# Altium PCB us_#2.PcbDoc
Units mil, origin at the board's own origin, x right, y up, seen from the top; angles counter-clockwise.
Board outline 1397.64 x 1968.5 mil, 2 copper layers (Top Layer, Bottom Layer); 60 components, 46 nets, 211 pads, 12 vias.
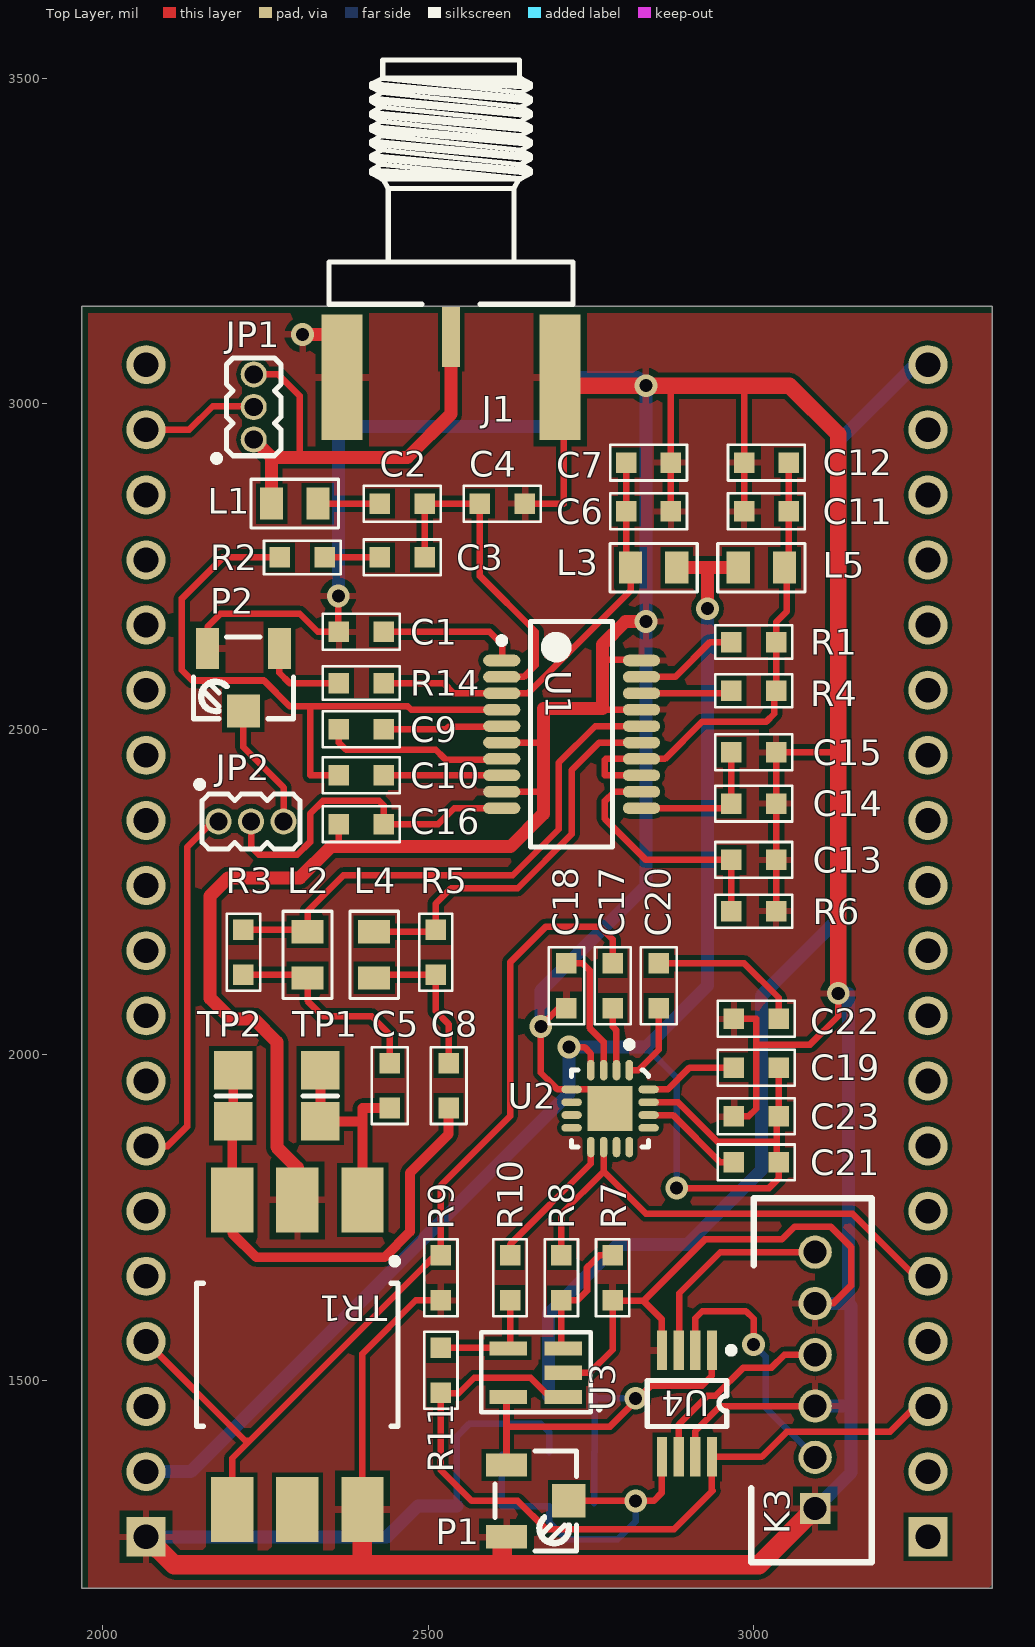
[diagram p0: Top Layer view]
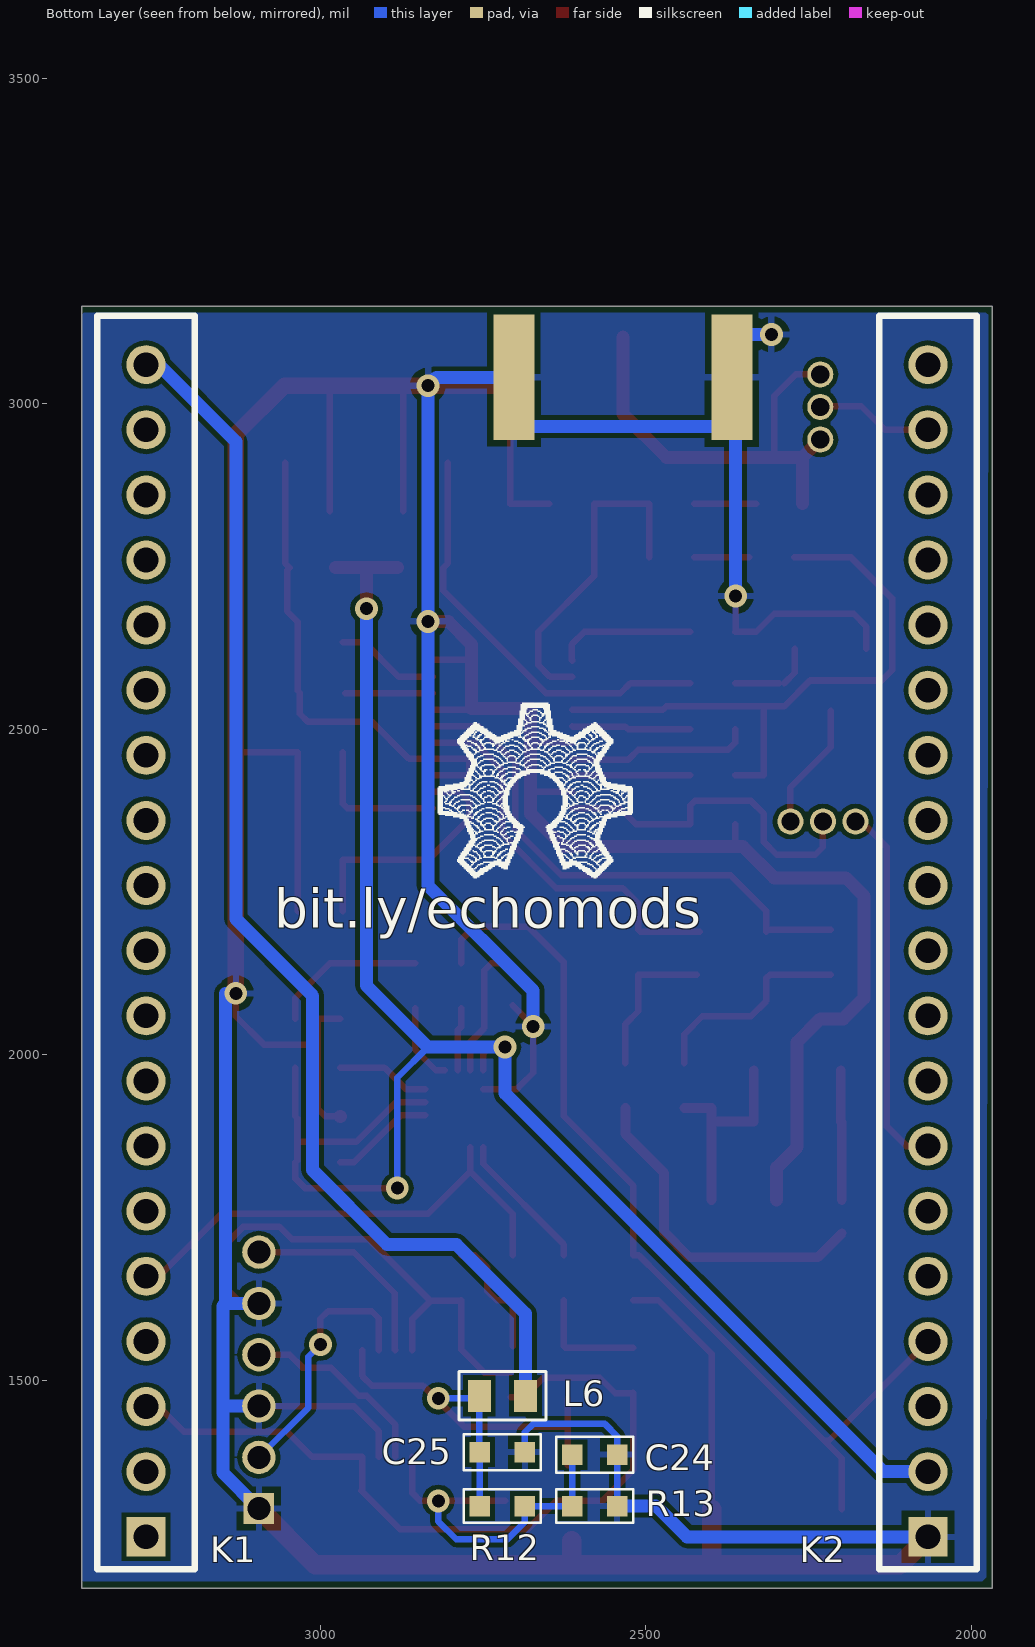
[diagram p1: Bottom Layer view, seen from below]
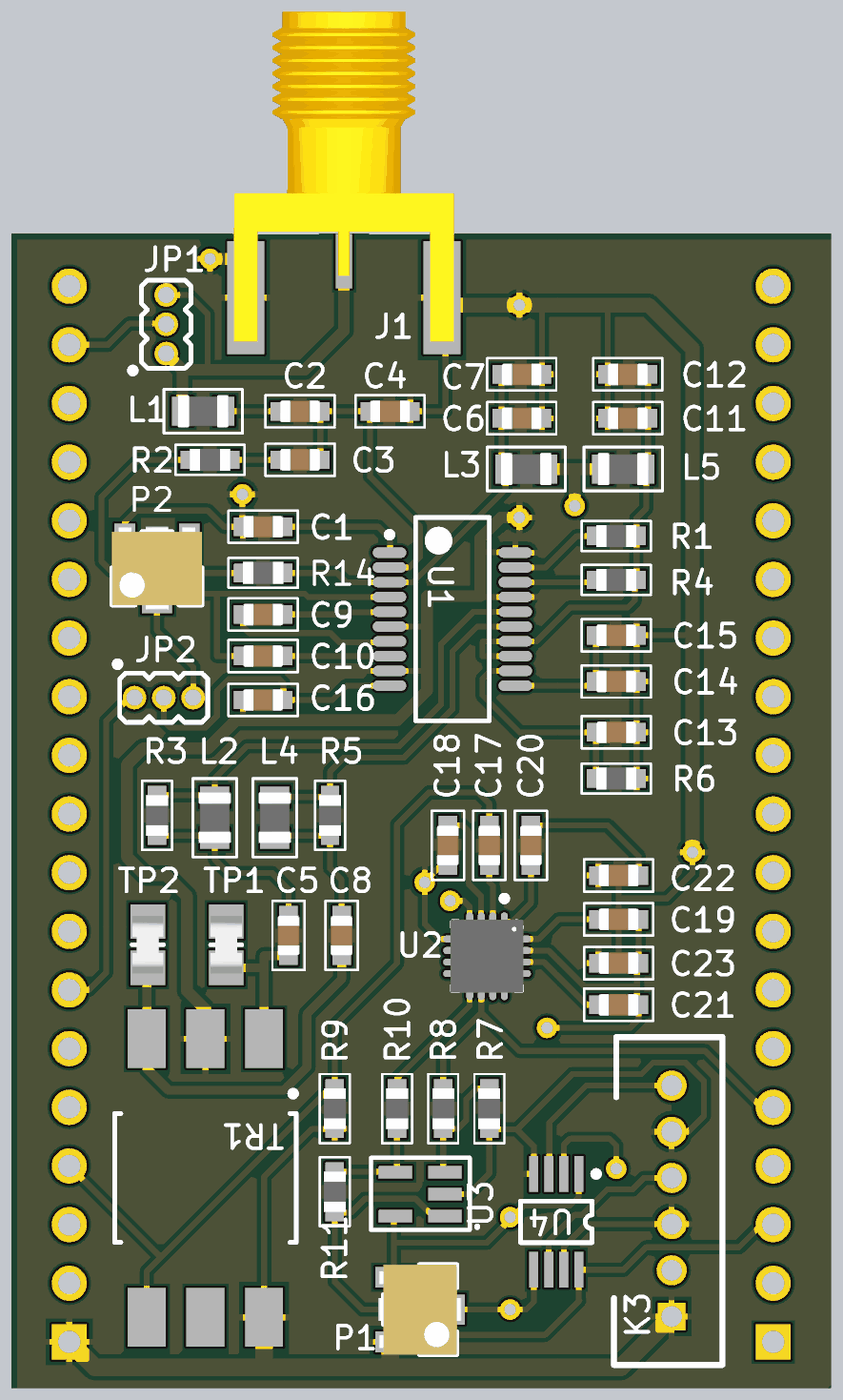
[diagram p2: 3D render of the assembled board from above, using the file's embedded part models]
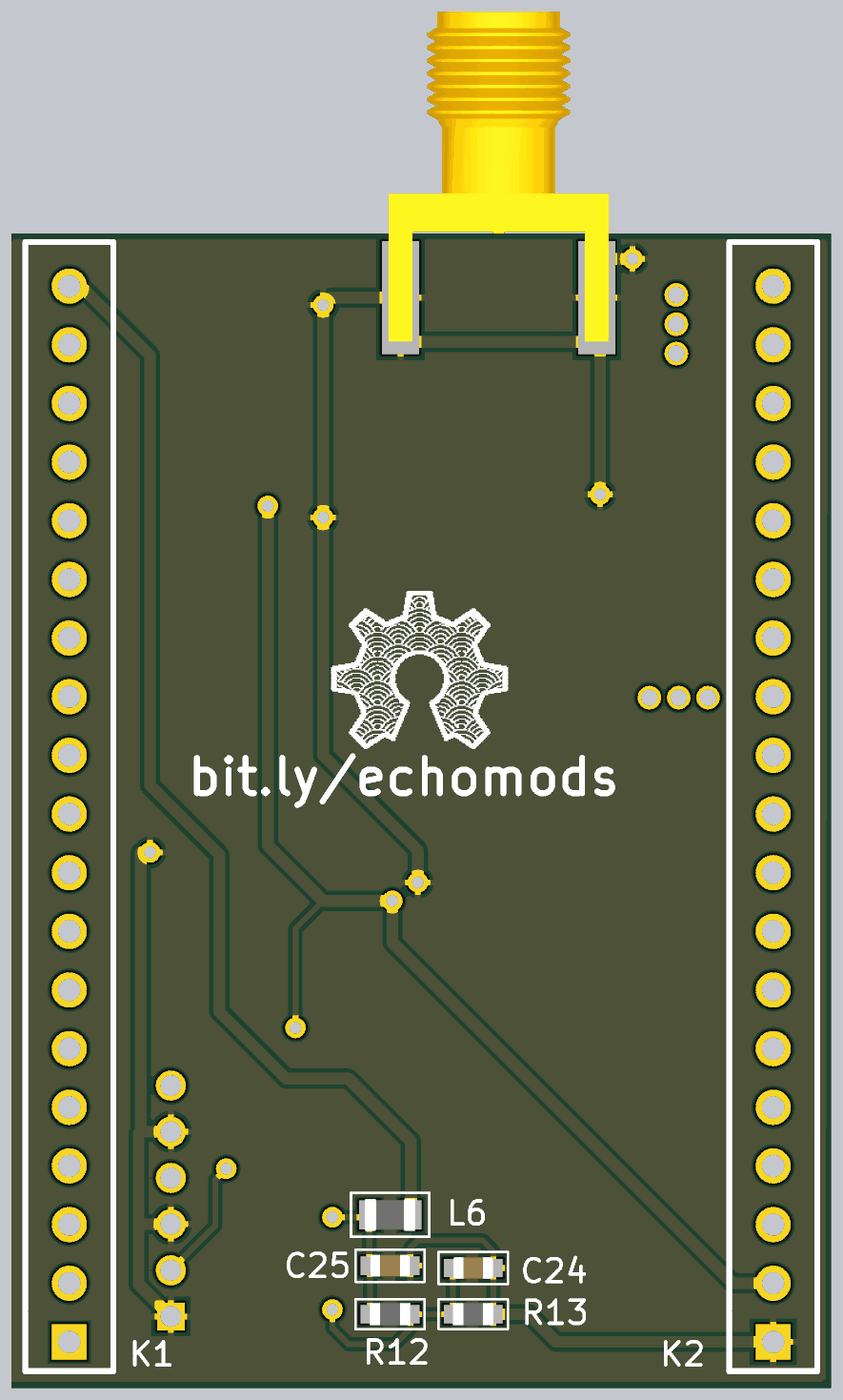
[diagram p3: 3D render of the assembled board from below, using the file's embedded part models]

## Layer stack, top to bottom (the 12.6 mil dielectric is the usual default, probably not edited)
Top Solder: solder mask 0.4, Solder Resist, Dk 3.5
Top Layer: signal copper 1.4
Dielectric 1: dielectric 12.6, FR-4, Dk 4.8
Bottom Layer: signal copper 1.4
Bottom Solder: solder mask 0.4, Solder Resist, Dk 3.5

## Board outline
1968.5,1181.1 3366.14,1181.1 3366.14,3149.61 1968.5,3149.61

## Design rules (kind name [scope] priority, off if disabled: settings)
Clearance [All] p1: gap=7
DiffPairsRouting [All] p1: maxlimit=10 minlimit=10 mostfreqgap=10 toplayer_minwidth=15 toplayer_maxwidth=15 toplayer_prefwidth=15 bottomlayer_minwidth=15 bottomlayer_maxwidth=15 bottomlayer_prefwidth=15 maxuncoupledlength=500
MinimumSolderMaskSliver [All] p1: minsoldermaskwidth=0
PolygonConnect [All] p1: connectstyle=Relief reliefconductorwidth=10 reliefentries=4 polygonreliefangle="90 Angle" airgapwidth=10
RoutingVias [All] p1: holewidth=20 width=35 viastyle="Through Hole" minholewidth=20 minwidth=35 maxholewidth=28 maxwidth=50
SilkToSilkClearance [All] p1: silktosilkclearance=7
SilkToSolderMaskClearance [IsPad] p1: minsilkscreentomaskgap=4 clearancetoexposedcopper=TRUE
SolderMaskExpansion [All] p1: expansion=4
Width [All] p1: maxlimit=40 minlimit=10 preferedwidth=10
25 further rules are at their usual default settings.

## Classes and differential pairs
net class RF: NetC2_1 NetC2_2 NetC5_2 NetC8_1 NetC17_2 NetL2_2 NetL4_2 VGA_OUT_N VGA_OUT_P
differential pair VGA_OUT: +VGA_OUT_P -VGA_OUT_N

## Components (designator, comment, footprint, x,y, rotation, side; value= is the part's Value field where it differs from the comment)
C1 "cap0603" "SM0603 _3D_cap" 2397.64,2649.61 r0 top
C2 "cap0603" "SM0603 _3D_cap" 2460.63,2846.46 r180 top
C3 "cap0603" "SM0603 _3D_cap" 2460.63,2763.78 r0 top
C4 "cap0603" "SM0603 _3D_cap" 2614.17,2846.46 r180 top
C5 "cap0603" "SM0603 _3D_cap" 2440.94,1952.76 r90 top
C6 "cap0603" "SM0603 _3D_cap" 2838.58,2834.65 r180 top
C7 "cap0603" "SM0603 _3D_cap" 2838.58,2909.45 r180 top
C8 "cap0603" "SM0603 _3D_cap" 2531.5,1952.76 r270 top
C9 "cap0603" "SM0603 _3D_cap" 2397.64,2500 r0 top
C10 "cap0603" "SM0603 _3D_cap" 2397.64,2429.13 r180 top
C11 "cap0603" "SM0603 _3D_cap" 3019.68,2834.65 r0 top
C12 "cap0603" "SM0603 _3D_cap" 3019.68,2909.45 r0 top
C13 "cap0603" "SM0603 _3D_cap" 3000,2299.21 r180 top
C14 "cap0603" "SM0603 _3D_cap" 3000,2385.83 r180 top
C15 "cap0603" "SM0603 _3D_cap" 3000,2464.57 r180 top
C16 "cap0603" "SM0603 _3D_cap" 2397.64,2354.33 r0 top
C17 "cap0603" "SM0603 _3D_cap" 2783.46,2106.3 r270 top
C18 "cap0603" "SM0603 _3D_cap" 2712.6,2106.3 r90 top
C19 "cap0603" "SM0603 _3D_cap" 3003.94,1980.32 r180 top
C20 "cap0603" "SM0603 _3D_cap" 2854.33,2106.3 r270 top
C21 "cap0603" "SM0603 _3D_cap" 3003.94,1834.65 r180 top
C22 "cap0603" "SM0603 _3D_cap" 3003.94,2055.12 r0 top
C23 "cap0603" "SM0603 _3D_cap" 3003.94,1905.51 r0 top
C24 "cap0603" "SM0603 _3D_cap" 2578.74,1385.83 r0 bottom
C25 "cap0603" "SM0603 _3D_cap" 2720.47,1389.76 r0 bottom
J1 "SMA" AMPHENOL_132357-11 2535.43,3102.36 r270 top
JP1 "Family" SULLINS_GRPB031VWVN 2232.28,2944.88 r90 top (schematic designator Jumper1)
JP2 "Family" SULLINS_GRPB031VWVN 2178.15,2358.27 r0 top (schematic designator Jumper2)
K1 "PLS_2.54mm-19" PLS_2.54mm-19 3267.72,1259.84 r180 bottom
K2 "PLS_2.54mm-19" PLS_2.54mm-19 2066.93,1259.84 r180 bottom
K3 "Molex_89400_061" Molex_89400-061 3094.49,1303.15 r180 top
L1 "75R@100MHz" "SM_0805_INDUCTANCE _3D" 2295.28,2846.46 r180 top
L2 "75R@100MHz" "SM_0805_INDUCTANCE _3D" 2314.96,2153.54 r90 top
L3 "75R@100MHz" "SM_0805_INDUCTANCE _3D" 2846.46,2748.03 r0 top
L4 "75R@100MHz" "SM_0805_INDUCTANCE _3D" 2417.32,2153.54 r90 top
L5 "75R@100MHz" "SM_0805_INDUCTANCE _3D" 3011.81,2748.03 r0 top
L6 "75R@100MHz" "SM_0805_INDUCTANCE _3D" 2720.47,1476.38 r0 bottom
P1 "5k" TRIM_BOURNS_3223W 2665.35,1314.96 r270 top
P2 "5k" TRIM_BOURNS_3223W 2216.54,2578.74 r180 top
R1 "10k" SM0603_3D_res 3000,2633.86 r180 top
R2 "280" SM0603_3D_res 2307.09,2763.78 r0 top
R3 "100" SM0603_3D_res 2216.54,2157.48 r90 top
R4 "10k" SM0603_3D_res 3000,2559.06 r180 top
R5 "100" SM0603_3D_res 2511.81,2157.48 r90 top
R6 "11k" SM0603_3D_res 3000,2220.47 r180 top
R7 "13k" SM0603_3D_res 2783.46,1657.48 r270 top
R8 "5k1" SM0603_3D_res 2704.72,1657.48 r270 top
R9 "75" SM0603_3D_res 2519.68,1657.48 r90 top
R10 "5k1" SM0603_3D_res 2625.98,1657.48 r270 top
R11 "13k" SM0603_3D_res 2519.68,1515.75 r270 top
R12 "1k1" SM0603_3D_res 2720.47,1307.09 r0 bottom
R13 "9k8" SM0603_3D_res 2578.74,1307.09 r0 bottom
R14 "20k" SM0603_3D_res 2397.64,2570.87 r0 top
TP1 "Test Point" NICOMATIC_C12000B 2334.65,1937.01 r90 top
TP2 "Test Point" NICOMATIC_C12000B 2200.79,1937.01 r90 top
TR1 "1:1" XFMR_MINI-CIRCUITS_KK81 2299.21,1539.37 r180 top
U1 "AD8331ARQZ" SOP64P600X175-20N 2720.47,2492.13 r0 top
U2 "ADL5511ACPZ-R7" QFN50P300X300X80-17N-S175 2779.53,1917.32 r270 top
U3 "AD8691" TSOT-5(RT-5) 2665.35,1511.81 r90 top
U4 "AD7274" RM-8 2897.64,1464.57 r180 top

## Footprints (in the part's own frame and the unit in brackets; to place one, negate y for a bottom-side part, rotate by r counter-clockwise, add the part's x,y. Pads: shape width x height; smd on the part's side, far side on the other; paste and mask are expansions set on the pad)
AMPHENOL_132357-11 [mm]
  rect 2.35x0.7 smd: 1(0,0)
  rect 4.9x1.6 smd: 2(1.575,4.25) 2(1.575,-4.25)
  rect 4.9x1.6 smd far side: 2(1.575,4.25) 2(1.575,-4.25)
  silkscreen extent -10.81,-4.76 -1.28,4.76, body extent -10.8,-4.76 3.48,4.76, height 4.08
Molex_89400-061 [mm] "vertical 6 pin 2mm pitch"
  rect 1.2x1.2 hole 0.9: 1(0,0)
  round 1.3 hole 0.9: 2(0,-2) 3(0,-4) 4(0,-6) 5(0,-8) 6(0,-10)
  silkscreen extent -2.2,-12.1 2.5,2.1
NICOMATIC_C12000B [mm]
  rect 1.5x1.5 smd: 1(-1,0) 1(1,0)
  silkscreen extent 0,-0.67 0,0.67, body extent -1.25,-0.67 1.25,0.68, height 1.5
PLS_2.54mm-19 [mil] "soldering pads"
  rect 60x60 hole 38: 1(0,0)
  round 60 hole 38: 2(0,100) 3(0,200) 4(0,300) 5(0,400) 6(0,500) 7(0,600) 8(0,700) 9(0,800) 10(0,900) 11(0,1000) 12(0,1100) 13(0,1200) 14(0,1300) 15(0,1400) 16(0,1500) 17(0,1600) 18(0,1700) 19(0,1800)
  silkscreen extent -75,-50 75,1875
QFN50P300X300X80-17N-S175 [mm]
  oval 0.8x0.3 smd: 1(-1.5,0.75) 2(-1.5,0.25) 3(-1.5,-0.25) 4(-1.5,-0.75) 9(1.5,-0.75) 10(1.5,-0.25) 11(1.5,0.25) 12(1.5,0.75)
  oval 0.3x0.8 smd: 5(-0.75,-1.5) 6(-0.25,-1.5) 7(0.25,-1.5) 8(0.75,-1.5) 13(0.75,1.5) 14(0.25,1.5) 15(-0.25,1.5) 16(-0.75,1.5)
  rect 1.75x1.75 smd: 17(0,0)
  silkscreen extent -2.62,-1.5 1.5,1.5, body extent -1.57,-1.57 1.58,1.58, height 0.8
RM-8 [mm] "Shrink Small Outline, MSOP; 8 Leads; Body Width 3 mm; Pitch 0.65 mm"
  rect 0.4x1.55 smd: 1(-0.975,-2.075) 2(-0.325,-2.075) 3(0.325,-2.075) 4(0.975,-2.075) 5(0.975,2.075) 6(0.325,2.075) 7(-0.325,2.075) 8(-0.975,2.075)
  silkscreen extent -1.85,-2.2 1.55,0.9, body extent -1.63,-1.6 1.63,1.6, height 1.1
"SM0603 _3D_cap" [mm] "standard  0603 inch size"
  rect 0.8x0.8 smd: 1(-0.875,0) 2(0.875,0)
  silkscreen extent -1.5,-0.7 1.5,0.7, body extent -0.87,-0.47 0.88,0.48, height 0.87
SM0603_3D_res [mm] "0603 inch resistor"
  rect 0.8x0.8 smd: 1(-0.875,0) 2(0.875,0)
  silkscreen extent -1.5,-0.65 1.5,0.65, body extent -0.87,-0.47 0.88,0.48, height 0.55
"SM_0805_INDUCTANCE _3D" [mm] "chip inductanse 0805 inch"
  rect 0.9x1.25 smd: 1(-0.9,0) 2(0.9,0)
  silkscreen extent -1.7,-0.95 1.7,0.95, body extent -1.1,-0.7 1.1,0.7, height 1.1
SOP64P600X175-20N [mm]
  oval 1.45x0.45 smd: 1(-2.725,2.88) 2(-2.725,2.24) 3(-2.725,1.6) 4(-2.725,0.96) 5(-2.725,0.32) 6(-2.725,-0.32) 7(-2.725,-0.96) 8(-2.725,-1.6) 9(-2.725,-2.24) 10(-2.725,-2.88) 11(2.725,-2.88) 12(2.725,-2.24) 13(2.725,-1.6) 14(2.725,-0.96) 15(2.725,-0.32) 16(2.725,0.32) 17(2.725,0.96) 18(2.725,1.6) 19(2.725,2.24) 20(2.725,2.88)
  silkscreen extent -2.85,-4.4 1.6,4.4, body extent -2,-4.4 2,4.4, height 1.75
SULLINS_GRPB031VWVN [mil]
  round 40 hole 28: 1(0,0) 2(50,0) 3(100,0)
  silkscreen extent -33,-42 125,61
TRIM_BOURNS_3223W [mm]
  rect 0.9x1.6 smd: 1(-1.4,-1.14) 3(1.4,-1.14)
  rect 1.3x1.3 smd: 2(0,1.29)
  silkscreen extent -1.95,-1.59 1.95,1.59, body extent -1.95,-1.81 1.95,1.81, height 4.16
TSOT-5(RT-5) [mm] "SOT-23/SC-74A; 5 Leads; Body 3.1 x 3 mm, inc. leads (LxW max)"
  rect 0.55x1.45 smd: 1(-0.95,-1.075) 2(0,-1.075) 3(0.95,-1.075) 4(0.95,1.075) 5(-0.95,1.075)
  silkscreen extent -1.55,-2.47 1.58,2.12, body extent -1.63,-0.98 1.65,1.05, height 1
XFMR_MINI-CIRCUITS_KK81 [mil]
  rect 64.96x100 smd: 1(-100,-237.5) 2(0,-237.5) 3(100,-237.5) 4(100,237.5) 5(0,237.5) 6(-100,237.5)
  silkscreen extent -155,-149 155,110

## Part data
C1 C2 C3 C4 C5 C6 C7 C8 C9 C10 C11 C12 C13 C14 C15 C16 C17 C18 C19 C20 C21 C22 C23 C24 C25: "Capacitor  0603 inch"
J1: library part Coax_1Female_1Shield
JP1 JP2: library part SULLINS_GRPB031VWVN, "Connector 3 Male"
K3: "6 pin vertical 2mm"
L1 L2 L3 L4 L5 L6: library part Ind_Chip, "chip inductance"
P1 P2: library part "Trimming Potentiometer", "Trimming Potentiometer"
R1 R2 R3 R4 R5 R6 R7 R8 R9 R10 R11 R12 R13 R14: library part Res_0603_1%_EU, "Res_0603_1%_EU"
TP1 TP2: library part NICOMATIC_C12000B
TR1: library part XFMR_MINI-CIRCUITS_T1-6T-KK81, "50 Ohm 0.015 To 300MHz RF Transformers"
U2: "DC to 6 GHz Envelope and TruPwr RMS Detector"
U3: library part OpAmp_TSOT5
U4: "adc serial"

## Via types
v1: diameter 35, hole 20, Top Layer to Bottom Layer, 12 vias

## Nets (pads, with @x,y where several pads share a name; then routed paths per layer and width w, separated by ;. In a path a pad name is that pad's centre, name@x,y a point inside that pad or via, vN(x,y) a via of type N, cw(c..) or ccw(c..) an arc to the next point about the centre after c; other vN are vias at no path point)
3.3VA: C25.2 L6.2 P1.1 R12.2 U3.5 U4.1 | length 717.9
  Top Layer w10: P1.1 2620.47,1429.13 ; U3.5@2620.47,1471.85 2620.47,1429.13 ; U4.1 2936.02,1506.89 2921.26,1492.13 2842.52,1492.13 2779.53,1429.13 2620.47,1429.13
  Bottom Layer w10: R12.2@2754.92,1311.02 C25.2 ; C25.2@2755.91,1390.74 L6.2 2759.84,1472.44 v1(2818.9,1472.44)
ADC: K1.3 R11.2 U3.1 U4.8 | length 1203.9
  Top Layer w10: R11.2 2519.68,1362.2 2566.93,1314.96 2637.8,1314.96 2681.1,1271.65 2877.95,1271.65 2937.01,1330.71 2936.02,1331.69 U4.8 3012.8,1382.87 3051.18,1421.26 3209.45,1421.26 K1.3@3248.03,1459.84 ; R11.2@2520.67,1480.32 2547.24,1480.32 2570.87,1503.94 2657.48,1503.94 2687.01,1474.41 U3.1
ADC_VREF: C24.2 P1.2 R12.1 R13.2 U4.5 | length 566.5
  Top Layer w10: P1.2 v1(2818.9,1314.96) 2846.46,1314.96 2859.25,1327.76 U4.5
  Bottom Layer w10: C24.2 R13.2 R12.1 2686.03,1282.48 2712.6,1255.91 2791.34,1255.91 2818.9,1283.46 v1(2818.9,1314.96)
AGND: C1.1 C4.1 C6.1 C7.1 C11.1 C12.1 C13.1 C14.1 C15.1 C16.1 C18.1 C22.1 C23.1 C24.1 C25.1 J1.2 K2.1 K3.1 K3.3 K3.5 P1.3 P2.3 R6.1 R7.2 R9.1 R13.1 TR1.2 TR1.6 U1.6 U1.9 U1.17 U1.20 U2.5 U2.17 U3.2 U4.4 U4.7 | length 11352.5
  Top Layer w10: P2.3 2161.42,2657.48 2181.1,2677.17 2303.15,2677.17 2330.71,2649.61 C1.1 2362.2,2650.6 v1(2362.2,2704.72) ; 2363.19,2319.88 C16.1 ; TR1.6 2399.21,1540.94 2481.3,1623.03 R9.1 ; U1.9 2675.59,2403.94 2677.17,2405.51 ; U1.6 2676.38,2479.53 2677.17,2480.32 ; C4.1 2708.66,2846.45 J1.2@2708.66,3034.45 ; v1@2673.23,2044.3 C18.1@2704.72,2075.79 ; v1@2673.23,2048.23 v1(2673.23,2043.31) 2673.23,1972.44 2690.94,1954.72 2698.82,1946.85 U2.5 U2.17@2750,1946.85 ; U3.2 2748.03,1511.81 2783.46,1547.24 R7.2 ; 2767.72,2531.5 2769.29,2529.92 U1.17 ; 2767.72,2606.3 2826.97,2606.3 U1.20 ; R7.2@2784.45,1622.05 2830.71,1622.05 ; U4.4 2859.25,1593.5 2830.71,1622.05 ; C6.1 C7.1 2873.03,3027.56 ; U4.7 2910.43,1422.24 2948.82,1460.63 K3.3 ; C23.1@2968.5,1905.51 C23.1 2992.13,1905.51 3003.94,1917.32 3003.94,2015.75 ; C22.1 3003.94,2055.12 3003.94,2015.75 ; C11.1 C12.1 2985.24,3026.57 ; R6.1 C13.1 C14.1 C15.1 3125.99,2464.56 ; K3.5 3122.05,1618.11 3149.61,1645.67 3149.61,1704.72 3118.11,1736.22 3062.99,1736.22 3043.31,1716.54 2925.2,1716.54 2830.71,1622.05 ; v1(3129.92,2094.49) 3129.92,2059.06 3086.61,2015.75 3003.94,2015.75
  Top Layer w20: TR1.2 2299.21,1826.77 2267.72,1858.27 2267.72,2019.68 2232.28,2055.12 2196.85,2055.12 2165.35,2086.61 2165.35,2244.09 2192.91,2271.65 2303.15,2271.65 2351.38,2319.88 2363.19,2319.88 2626.97,2319.88 2677.17,2370.08 2677.17,2402.36 ; v1(2307.09,3106.3) 2307.09,3101.38 2302.17,3106.3 J1.2@2370.08,3106.3 ; 2677.17,2405.51 2677.17,2480.32 2677.17,2531.5 2767.72,2531.5 2767.72,2606.3 2767.72,2629.86 2803.21,2665.35 v1(2834.65,2665.35)
  Top Layer w25: J1.2@2702.76,3040.35 2708.66,3034.45 2715.55,3027.56 v1(2834.65,3027.56) 2873.03,3027.56 3055.12,3027.56 3129.92,2952.76 v1(3129.92,2094.49)
  Top Layer w30: K2.1 2110.24,1216.54 2614.17,1216.54 ; 2399.21,1222.05 TR1.6 ; P1.3@2614.17,1253.54 2614.17,1216.54 ; K3.1 3007.87,1216.54 2614.17,1216.54
  Bottom Layer w10: R13.1 C24.1 2544.29,1414.37 2562.99,1433.07 2673.23,1433.07 2686.03,1420.27 C25.1 ; 3145.67,1618.11 3149.61,1614.17
  Bottom Layer w20: K2.1@2074.8,1259.84 2437.01,1259.84 2484.25,1307.08 R13.1 ; v1(2307.09,3106.3) J1.2@2342.52,3106.3 ; v1(2362.2,2704.72) J1.2@2362.2,3034.45 ; J1.2@2377.95,2964.57 J1.2@2712.6,2964.57 ; v1(2673.23,2043.31) 2673.23,2098.43 2834.65,2259.84 v1(2834.65,2665.35) v1(2834.65,3027.56) 2821.85,3040.35 J1.2@2702.76,3040.35 ; K3.1 3149.61,1358.27 3149.61,1460.63 ; K3.3 3149.61,1460.63 ; K3.5 3145.67,1618.11 3145.67,2094.49 v1(3129.92,2094.49) ; 3149.61,1614.17 3149.61,1460.63
  Bottom Layer w30: K2.1 K2.1@2074.8,1259.84
GAIN: JP2.1 K2.7 | length 560.2
  Top Layer w10: K2.7 2100,1859.84 2129.92,1889.76 2129.92,2318.9 JP2.1@2169.29,2358.27
NetC1_2: C1.2 U1.1 | length 215.1
  Top Layer w10: C1.2 2594.49,2649.61 2614.17,2629.92 2614.17,2606.5 U1.1
NetC2_1: C2.1 C3.2 C4.2 U1.2 | length 510.5
  Top Layer w10: C3.2 C2.1 C4.2 2579.72,2735.24 2665.35,2649.61 2665.35,2598.43 2647.24,2580.31 U1.2
NetC2_2: C2.2 L1.1 | length 95.5
  Top Layer w10: L1.1 C2.2
NetC3_1: C3.1 R2.2 | length 84.6
  Top Layer w10: R2.2 C3.1
NetC5_2: C5.2 L2.1 R3.1 | length 327.4
  Top Layer w10: R3.1 2310.04,2123.03 L2.1 2314.96,2082.68 2338.58,2059.06 2413.39,2059.06 2440.94,2031.5 C5.2
NetC6_2: C6.2 C7.2 L3.1 R14.2 U1.3 | length 650.4
  Top Layer w10: R14.2 2523.62,2570.87 2539.37,2555.12 U1.3 2653.54,2555.12 2811.02,2712.6 L3.1 2804.13,2754.92 C6.2 C7.2
NetC8_1: C8.1 L4.1 R5.1 | length 233.5
  Top Layer w10: L4.1@2422.25,2123.03 R5.1 2511.81,2066.93 2531.5,2047.24 C8.1
NetC9_1: C9.1 U1.7 | length 282.3
  Top Layer w10: C9.1 2363.19,2479.33 2374.02,2468.5 2511.81,2468.5 2523.62,2456.69 2527.56,2452.76 2611.61,2452.76 U1.7
NetC9_2: C9.2 U1.5 | length 183.1
  Top Layer w10: C9.2 2527.56,2500 2531.5,2503.94 2612.4,2503.94 U1.5
NetC10_1: C10.1 U1.8 | length 181.1
  Top Layer w10: C10.1 2535.43,2429.13 U1.8
NetC10_2: C10.2 R2.1 U1.4 | length 953.8
  Top Layer w10: R2.1 2185.04,2763.78 2122.05,2700.79 2122.05,2590.55 2137.8,2574.8 2248.03,2574.8 2287.4,2535.43 2318.9,2535.43 ; C10.2 2318.9,2429.13 2318.9,2535.43 ; U1.4 2474.02,2529.92 2468.5,2535.43 2318.9,2535.43
NetC11_2: C11.2 C12.2 L5.2 R1.1 R4.1 U1.13 U1.14 | length 761.8
  Top Layer w10: U1.13 2771.65,2429.13 2771.65,2452.76 2773.23,2454.33 U1.14 2863.78,2454.33 2921.26,2511.81 3019.69,2511.81 3031.5,2523.62 3031.5,2556.1 R4.1 R1.1 3034.45,2664.37 3051.18,2681.1 L5.2@3051.18,2744.09 ; L5.2 3054.14,2754.92 C11.2 C12.2
NetC13_2: C13.2 R6.2 U1.12 | length 388.3
  Top Layer w10: U1.12 2785.83,2403.94 2771.65,2389.76 2771.65,2362.2 2834.65,2299.21 C13.2 R6.2
NetC14_2: C14.2 C15.2 U1.11 | length 219.5
  Top Layer w10: U1.11 2958.47,2378.74 C14.2 C15.2
NetC16_2: C16.2 JP2.2 U1.10 | length 534
  Top Layer w10: JP2.2@2219.29,2358.27 2228.35,2349.21 2228.35,2318.9 2240.16,2307.09 2299.21,2307.09 2318.9,2326.77 2318.9,2370.08 2338.58,2389.76 2425.2,2389.76 2432.09,2382.87 C16.2 2515.75,2354.33 2540.16,2378.74 U1.10
NetC17_2: C17.2 U2.2 | length 97.9
  Top Layer w10: C17.2 2783.47,2043.3 2789.37,2037.4 U2.2
NetC18_2: C18.2 U2.3 | length 202.2
  Top Layer w10: C18.2 2737.2,2140.75 2748.03,2129.92 2748.03,2041.18 2769.53,2019.68 U2.3@2769.53,1976.53
NetC19_2: C19.2 U2.16 | length 144.8
  Top Layer w10: U2.16 2868.11,1946.85 2901.57,1980.32 ; 2901.58,1980.31 C19.2
NetC20_1: C20.1 C22.2 | length 238.5
  Top Layer w10: C20.1 2985.24,2140.75 3038.39,2087.6 C22.2
NetC20_2: C20.2 U2.1 | length 122.3
  Top Layer w10: U2.1 2822.83,1976.38 2854.33,2007.87 C20.2
NetC21_2: C21.2 U2.14 | length 161.1
  Top Layer w10: U2.14 2875.98,1907.48 2948.82,1834.64 C21.2
NetJ1_1: J1.1 JP1.1 JP1.3 L1.2 | length 710.3
  Top Layer w10: JP1.3 2270.08,3044.88 2303.15,3011.81 2303.15,2917.32
  Top Layer w20: JP1.1 2259.84,2917.32 ; L1.2 2259.84,2917.32 ; J1.1 2535.43,2984.25 2468.5,2917.32 2303.15,2917.32 2259.84,2917.32
NetJumper2_3: JP2.3 P2.2 | length 199.2
  Top Layer w10: P2.2 2216.54,2472.44 2278.54,2410.43 2278.54,2367.52 JP2.3@2269.29,2358.27
NetK3_2: K3.2 U4.2 | length 399.9
  Top Layer w10: U4.2 2910.43,1595.47 2921.26,1606.3 2988.19,1606.3 3000,1594.49 v1(3000,1555.12)
  Bottom Layer w10: v1(3000,1555.12) 3018.69,1536.42 3018.69,1457.68 K3.2
NetK3_4: K3.4 U4.6 | length 303.3
  Top Layer w10: U4.6 2884.84,1432.09 2901.57,1448.82 2929.13,1476.38 2940.94,1476.38 2984.25,1519.68 3027.56,1519.68 3047.24,1539.37 K3.4
NetK3_6: K3.6 U4.3 | length 322.8
  Top Layer w10: U4.3 2885.83,1547.24 2885.83,1633.86 2948.82,1696.85 K3.6
NetL2_2: L2.2 R3.2 U1.16 | length 817.5
  Top Layer w10: R3.2 L2.2@2312.01,2191.93 ; L2.2 2314.96,2220.47 2370.08,2275.59 2629.92,2275.59 2700.79,2346.46 2700.79,2448.82 2756.69,2504.72 U1.16
NetL4_2: L4.2 R5.2 U1.15 | length 607.9
  Top Layer w10: L4.2 R5.2@2508.85,2188.98 ; R5.2 2511.81,2232.28 2535.43,2255.91 2637.8,2255.91 2720.47,2338.58 2720.47,2437.01 2762.99,2479.53 U1.15
NetP2_1: P2.1 R14.1 | length 127.2
  Top Layer w10: P2.1 2271.65,2586.61 2287.4,2570.86 ; 2295.28,2570.87 R14.1
NetR1_2: R1.2 U1.19 | length 160
  Top Layer w10: U1.19 2879.53,2580.31 2933.07,2633.86 R1.2
NetR4_2: R4.2 U1.18 | length 133.9
  Top Layer w10: U1.18 R4.2@2961.61,2555.12
NetR7_1: R7.1 R8.2 U3.3 | length 198.9
  Top Layer w10: U3.3@2704.73,1552.16 R8.2 2729.33,1623.03 2744.09,1637.8 2744.09,1673.23 2751.97,1681.1 2762.79,1691.93 R7.1
NetR10_1: R10.1 U2.9 | length 217.7
  Top Layer w10: R10.1 2625.98,1708.66 2750,1832.68 U2.9
NetR10_2: R10.2 R11.1 U3.4 | length 175.2
  Top Layer w10: R11.1 U3.4@2624.01,1550.19 ; U3.4@2625.99,1552.17 R10.2
V_ENVELOPE: K1.5 R8.1 U2.10 | length 745.5
  Top Layer w10: R8.1 2704.73,1755.91 2769.69,1820.87 ; U2.10 2769.69,1820.87 ; K1.5@3253.15,1654.72 3151.97,1755.91 2834.65,1755.91 2769.69,1820.87
VDD_3.3V: K1.19 L6.1 | length 1878.9
  Bottom Layer w20: L6.1 2685.04,1602.36 2791.34,1708.66 2897.64,1708.66 3011.81,1822.83 3011.81,2090.55 3129.92,2208.66 3129.92,2941.73 K1.19@3248.03,3059.84
VDD_5V: C19.1 C21.1 C23.2 K2.2 L3.2 L5.1 U2.4 U2.15 | length 2801.6
  Top Layer w10: v1(2716.54,2011.81) 2740.16,2011.81 2750,2001.97 U2.4 ; U2.15 2883.86,1927.17 2893.7,1917.32 2944.88,1866.14 3035.43,1866.14 ; v1(2881.89,1795.28) 3023.62,1795.28 3038.38,1810.04 C21.1 ; C21.1@3035.43,1837.59 3035.43,1866.14 ; C19.1 C23.2 3035.43,1902.56 3035.43,1866.14
  Top Layer w20: L3.2 2929.13,2748.03 ; v1(2929.13,2685.04) 2929.13,2748.03 ; L5.1 2929.13,2748.03
  Bottom Layer w10: 2834.65,2011.81 2881.89,1964.57 v1(2881.89,1795.28)
  Bottom Layer w20: K2.2 2135.43,1359.84 2716.54,1940.94 v1(2716.54,2011.81) 2834.65,2011.81 2929.13,2106.3 v1(2929.13,2685.04)
VGA_IN: JP1.2 K2.18 | length 180.8
  Top Layer w10: K2.18 2133.07,2959.84 2169.29,2996.06 2231.1,2996.06 JP1.2
VGA_OUT2: C17.1 K2.4 R9.2 TR1.4 | length 1469.3
  Top Layer w10: K2.4 2219.29,1407.48 2226.38,1407.48 ; TR1.4 2199.21,1380.31 2226.38,1407.48 ; C17.1 2783.47,2177.16 2763.78,2196.85 2681.1,2196.85 2625.98,2141.73 2625.98,1905.51 2519.68,1799.21 R9.2 2510.83,1691.93 2478.1,1659.2 2226.38,1407.48
VGA_OUT_N: C5.1 TP1.1 TR1.1 | length 322.5
  Top Layer w15: TP1.1@2334.65,1976.38 2334.65,1897.64 2395.28,1897.64 ; TR1.1 2399.21,1918.31 C5.1
VGA_OUT_P: C8.2 TP2.1 TR1.3 | length 717.2
  Top Layer w15: 2199.21,1725.98 2236.22,1688.98 2433.07,1688.98 2472.44,1728.35 2472.44,1818.9 2531.5,1877.96 C8.2 ; TR1.3 TP2.1@2199.21,1896.06 ; TP2.1@2200.79,1897.64 TP2.1@2200.79,1976.38
pads on no net: K1.1 K1.2 K1.4 K1.6 K1.7 K1.8 K1.9 K1.10 K1.11 K1.12 K1.13 K1.14 K1.15 K1.16 K1.17 K1.18 K2.3 K2.5 K2.6 K2.8 K2.9 K2.10 K2.11 K2.12 K2.13 K2.14 K2.15 K2.16 K2.17 K2.19 TR1.5 U2.6 U2.7 U2.8 U2.11 U2.12 U2.13

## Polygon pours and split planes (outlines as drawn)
AGND on Bottom Layer "Bottom Layer-No Net" (solid, pour order 2): 1974.41,3139.76 3363.12,3139.76 3366.14,3136.81 3366.14,1191.93 1983.46,1191.93 1977.43,1197.83
AGND on Top Layer "Bottom Layer-No Net" (solid, pour order 4): 1978.35,3138.78 3366.14,3138.78 3366.14,1187.04 3363.11,1184.07 3360.08,1181.1 1978.35,1181.1

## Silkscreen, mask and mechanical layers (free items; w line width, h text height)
Bottom Overlay:
  drawing of 1520 lines, arcs and shapes, not listed
  text "bit.ly/echomods" at 3070.87,2194.88 h60
Mechanical 1:
  lines w10: 1968.5,1181.1 3346.46,1181.1 3346.46,3149.61 1968.5,3149.61 1968.5,1181.1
